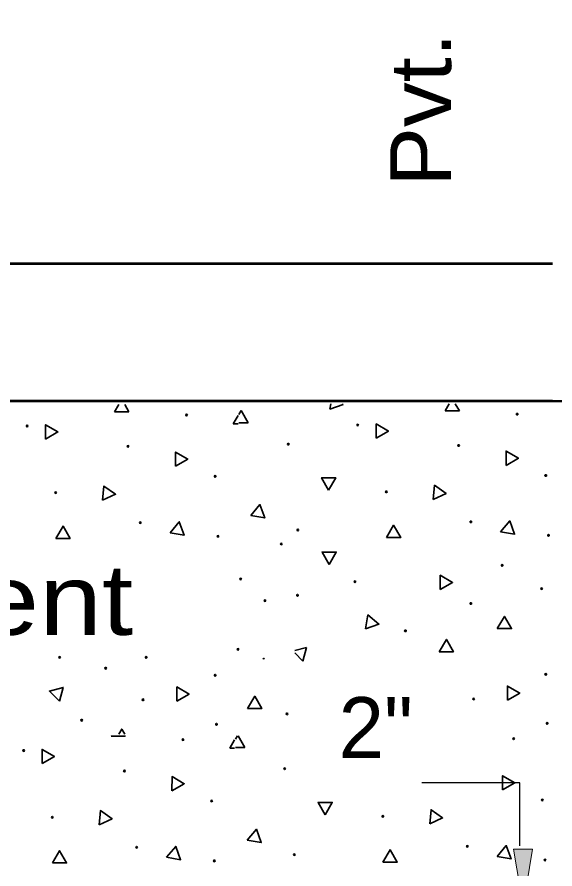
# Model space of a CAD drawing. Extents: x 72.6 to 107.3, y 36.1 to 58.1.
# Drawn here: x 92.859 to 94.034, y 53.623 to 55.484 of the extents above; entities that cross this region are included whole.
import ezdxf

# ---------------------------------------------------------------- set-up
doc = ezdxf.new("R2010")
doc.units = 0
doc.header["$LTSCALE"] = 0.053
doc.layers.add('1', color=7, linetype='Continuous', lineweight=35)
doc.layers.add('3', color=7, linetype='Continuous', lineweight=13)

msp = doc.modelspace()

# ---------------------------------------------------------------- hatches: boundary and pattern name
at = {"layer": '3'}
msp.add_hatch(color=256, dxfattribs=at).paths.add_polyline_path([(93.98483, 53.66683), (93.94317, 53.66683), (93.964, 53.54183), (93.964, 53.54183)])

# ---------------------------------------------------------------- linework, layer by layer
at = {"layer": '1', "lineweight": 53}
for p, q in [((90.01767, 54.94575), (94.0285, 54.94575)), ((90.01767, 54.94575), (94.0285, 54.94575)), ((90.01767, 54.64575), (94.0285, 54.64575))]:
    msp.add_line(p, q, dxfattribs=at)
at = {"layer": '1'}
for p, q in [((93.08117, 54.63742), (93.07217, 54.622)), ((93.08117, 54.63742), (93.07217, 54.622)), ((93.10333, 54.622), (93.09433, 54.63742)), ((93.10333, 54.622), (93.09433, 54.63742)), ((93.34867, 54.6245), (93.34367, 54.61583)), ((93.34867, 54.6245), (93.34367, 54.61583)), ((93.34867, 54.6245), (93.34367, 54.61583)), ((93.34867, 54.6245), (93.34367, 54.61583)), ((93.36417, 54.59767), (93.34867, 54.6245)), ((93.36417, 54.59767), (93.34867, 54.6245)), ((93.36417, 54.59767), (93.34867, 54.6245)), ((93.36417, 54.59767), (93.34867, 54.6245)), ((93.54433, 54.63933), (93.54217, 54.62717)), ((93.54433, 54.63933), (93.54217, 54.62717)), ((93.54433, 54.63933), (93.54217, 54.62717)), ((93.54433, 54.63933), (93.54217, 54.62717)), ((93.54217, 54.62717), (93.57133, 54.63783)), ((93.54217, 54.62717), (93.57133, 54.63783)), ((93.54217, 54.62717), (93.57133, 54.63783)), ((93.54217, 54.62717), (93.57133, 54.63783)), ((93.57133, 54.63783), (93.5695, 54.63933)), ((93.57133, 54.63783), (93.5695, 54.63933)), ((93.57133, 54.63783), (93.5695, 54.63933)), ((93.57133, 54.63783), (93.5695, 54.63933)), ((93.803, 54.63933), (93.794, 54.62392)), ((93.803, 54.63933), (93.794, 54.62392)), ((93.803, 54.63933), (93.794, 54.62392)), ((93.803, 54.63933), (93.794, 54.62392)), ((93.794, 54.62392), (93.82517, 54.62392)), ((93.794, 54.62392), (93.82517, 54.62392)), ((93.794, 54.62392), (93.82517, 54.62392)), ((93.794, 54.62392), (93.82517, 54.62392)), ((93.82517, 54.62392), (93.81617, 54.63933)), ((93.82517, 54.62392), (93.81617, 54.63933)), ((93.82517, 54.62392), (93.81617, 54.63933)), ((93.82517, 54.62392), (93.81617, 54.63933)), ((93.07217, 54.622), (93.10333, 54.622)), ((93.07217, 54.622), (93.10333, 54.622)), ((93.34183, 54.61392), (93.33125, 54.59575)), ((93.34183, 54.61392), (93.33125, 54.59575)), ((93.33125, 54.59575), (93.34183, 54.59575)), ((93.33125, 54.59575), (93.34183, 54.59575)), ((93.34367, 54.59767), (93.36417, 54.59767)), ((93.34367, 54.59767), (93.36417, 54.59767)), ((93.34367, 54.59767), (93.36417, 54.59767)), ((93.34367, 54.59767), (93.36417, 54.59767)), ((93.49158, 54.10717), (93.46567, 54.10025)), ((93.49158, 54.10717), (93.46567, 54.10025)), ((93.49158, 54.10717), (93.46567, 54.10025)), ((93.49158, 54.10717), (93.46567, 54.10025)), ((93.48358, 54.07717), (93.49158, 54.10717)), ((93.48358, 54.07717), (93.49158, 54.10717)), ((93.48358, 54.07717), (93.49158, 54.10717)), ((93.48358, 54.07717), (93.49158, 54.10717)), ((93.46567, 54.09517), (93.48358, 54.07717)), ((93.46567, 54.09517), (93.48358, 54.07717)), ((93.46567, 54.09517), (93.48358, 54.07717)), ((93.46567, 54.09517), (93.48358, 54.07717)), ((93.06517, 53.91433), (93.0645, 53.91317)), ((93.06517, 53.91433), (93.0645, 53.91317)), ((93.0645, 53.91317), (93.09567, 53.91317)), ((93.0645, 53.91317), (93.09567, 53.91317)), ((93.09567, 53.91317), (93.095, 53.91433)), ((93.09567, 53.91317), (93.095, 53.91433)), ((93.33417, 53.90508), (93.32358, 53.88692)), ((93.33417, 53.90508), (93.32358, 53.88692)), ((93.34025, 53.91433), (93.336, 53.907)), ((93.34025, 53.91433), (93.336, 53.907)), ((93.34025, 53.91433), (93.336, 53.907)), ((93.34025, 53.91433), (93.336, 53.907)), ((93.3565, 53.88883), (93.34175, 53.91433)), ((93.3565, 53.88883), (93.34175, 53.91433)), ((93.3565, 53.88883), (93.34175, 53.91433)), ((93.3565, 53.88883), (93.34175, 53.91433)), ((93.32358, 53.88692), (93.33417, 53.88692)), ((93.32358, 53.88692), (93.33417, 53.88692)), ((93.336, 53.88883), (93.3565, 53.88883)), ((93.336, 53.88883), (93.3565, 53.88883)), ((93.336, 53.88883), (93.3565, 53.88883)), ((93.336, 53.88883), (93.3565, 53.88883))]:
    msp.add_line(p, q, dxfattribs=at)
at = {"layer": '1', "lineweight": 25}
msp.add_line((93.957, 53.81142), (93.74308, 53.81142), dxfattribs=at)
at = {"layer": '1', "lineweight": 53}
msp.add_lwpolyline([(90.01767, 54.64575), (94.0285, 54.64575), (97.54775, 54.52283)], dxfattribs=at)
msp.add_lwpolyline([(90.01767, 54.64575), (94.0285, 54.64575), (97.54775, 54.52283)], dxfattribs=at)
at = {"layer": '1'}
for points in [[(92.9215, 54.56225), (92.94842, 54.57775), (92.92167, 54.59333)], [(92.9215, 54.56225), (92.94842, 54.57775), (92.92167, 54.59333)], [(93.64333, 54.56417), (93.67025, 54.57967), (93.6435, 54.59525)], [(93.64333, 54.56417), (93.67025, 54.57967), (93.6435, 54.59525)], [(93.64333, 54.56417), (93.67025, 54.57967), (93.6435, 54.59525)], [(93.64333, 54.56417), (93.67025, 54.57967), (93.6435, 54.59525)], [(93.20517, 54.50275), (93.23208, 54.51833), (93.20533, 54.53392)], [(93.20517, 54.50275), (93.23208, 54.51833), (93.20533, 54.53392)], [(93.927, 54.50467), (93.95392, 54.52025), (93.92717, 54.53583)], [(93.927, 54.50467), (93.95392, 54.52025), (93.92717, 54.53583)], [(93.927, 54.50467), (93.95392, 54.52025), (93.92717, 54.53583)], [(93.927, 54.50467), (93.95392, 54.52025), (93.92717, 54.53583)], [(93.5395, 54.45075), (93.55517, 54.47767), (93.52408, 54.47767)], [(93.5395, 54.45075), (93.55517, 54.47767), (93.52408, 54.47767)], [(93.5395, 54.45075), (93.55517, 54.47767), (93.52408, 54.47767)], [(93.5395, 54.45075), (93.55517, 54.47767), (93.52408, 54.47767)], [(93.04617, 54.42867), (93.07433, 54.44175), (93.049, 54.45958)], [(93.04617, 54.42867), (93.07433, 54.44175), (93.049, 54.45958)], [(93.768, 54.43058), (93.79617, 54.44367), (93.77083, 54.4615)], [(93.768, 54.43058), (93.79617, 54.44367), (93.77083, 54.4615)], [(93.768, 54.43058), (93.79617, 54.44367), (93.77083, 54.4615)], [(93.768, 54.43058), (93.79617, 54.44367), (93.77083, 54.4615)], [(93.3695, 54.39533), (93.40008, 54.38992), (93.3895, 54.41908)], [(93.3695, 54.39533), (93.40008, 54.38992), (93.3895, 54.41908)], [(93.3695, 54.39533), (93.40008, 54.38992), (93.3895, 54.41908)], [(93.3695, 54.39533), (93.40008, 54.38992), (93.3895, 54.41908)], [(93.91517, 54.35958), (93.94567, 54.35417), (93.93508, 54.38342)], [(93.91517, 54.35958), (93.94567, 54.35417), (93.93508, 54.38342)], [(93.91517, 54.35958), (93.94567, 54.35417), (93.93508, 54.38342)], [(93.91517, 54.35958), (93.94567, 54.35417), (93.93508, 54.38342)], [(92.944, 54.34525), (92.97508, 54.34525), (92.95967, 54.37208)], [(92.944, 54.34525), (92.97508, 54.34525), (92.95967, 54.37208)], [(93.19333, 54.35767), (93.22383, 54.35225), (93.21325, 54.3815)], [(93.19333, 54.35767), (93.22383, 54.35225), (93.21325, 54.3815)], [(93.66583, 54.34717), (93.69692, 54.34717), (93.6815, 54.374)], [(93.66583, 54.34717), (93.69692, 54.34717), (93.6815, 54.374)], [(93.66583, 54.34717), (93.69692, 54.34717), (93.6815, 54.374)], [(93.66583, 54.34717), (93.69692, 54.34717), (93.6815, 54.374)], [(93.54075, 54.2885), (93.55633, 54.31542), (93.52525, 54.31542)], [(93.54075, 54.2885), (93.55633, 54.31542), (93.52525, 54.31542)], [(93.54075, 54.2885), (93.55633, 54.31542), (93.52525, 54.31542)], [(93.54075, 54.2885), (93.55633, 54.31542), (93.52525, 54.31542)], [(93.78317, 54.23375), (93.81008, 54.24925), (93.78325, 54.26483)], [(93.78317, 54.23375), (93.81008, 54.24925), (93.78325, 54.26483)], [(93.78317, 54.23375), (93.81008, 54.24925), (93.78325, 54.26483)], [(93.78317, 54.23375), (93.81008, 54.24925), (93.78325, 54.26483)], [(93.62008, 54.1475), (93.64925, 54.15817), (93.6255, 54.178)], [(93.62008, 54.1475), (93.64925, 54.15817), (93.6255, 54.178)], [(93.62008, 54.1475), (93.64925, 54.15817), (93.6255, 54.178)], [(93.62008, 54.1475), (93.64925, 54.15817), (93.6255, 54.178)], [(93.90783, 54.14817), (93.93883, 54.14817), (93.92342, 54.175)], [(93.90783, 54.14817), (93.93883, 54.14817), (93.92342, 54.175)], [(93.90783, 54.14817), (93.93883, 54.14817), (93.92342, 54.175)], [(93.90783, 54.14817), (93.93883, 54.14817), (93.92342, 54.175)], [(93.78108, 54.09783), (93.81217, 54.09783), (93.79667, 54.12467)], [(93.78108, 54.09783), (93.81217, 54.09783), (93.79667, 54.12467)], [(93.78108, 54.09783), (93.81217, 54.09783), (93.79667, 54.12467)], [(93.78108, 54.09783), (93.81217, 54.09783), (93.79667, 54.12467)], [(92.952, 53.98983), (92.96, 54.01992), (92.93008, 54.01192)], [(92.952, 53.98983), (92.96, 54.01992), (92.93008, 54.01192)], [(93.208, 53.98992), (93.235, 54.00542), (93.20825, 54.02092)], [(93.208, 53.98992), (93.235, 54.00542), (93.20825, 54.02092)], [(93.92983, 53.99183), (93.95683, 54.00733), (93.93008, 54.02283)], [(93.92983, 53.99183), (93.95683, 54.00733), (93.93008, 54.02283)], [(93.92983, 53.99183), (93.95683, 54.00733), (93.93008, 54.02283)], [(93.92983, 53.99183), (93.95683, 54.00733), (93.93008, 54.02283)], [(93.3625, 53.97367), (93.39358, 53.97367), (93.37817, 54.0005)], [(93.3625, 53.97367), (93.39358, 53.97367), (93.37817, 54.0005)], [(93.3625, 53.97367), (93.39358, 53.97367), (93.37817, 54.0005)], [(93.3625, 53.97367), (93.39358, 53.97367), (93.37817, 54.0005)], [(92.91383, 53.85342), (92.94075, 53.86892), (92.914, 53.8845)], [(92.91383, 53.85342), (92.94075, 53.86892), (92.914, 53.8845)], [(93.1975, 53.79392), (93.22442, 53.8095), (93.19767, 53.82508)], [(93.1975, 53.79392), (93.22442, 53.8095), (93.19767, 53.82508)], [(93.91933, 53.79583), (93.94625, 53.81142), (93.9195, 53.827)], [(93.91933, 53.79583), (93.94625, 53.81142), (93.9195, 53.827)], [(93.91933, 53.79583), (93.94625, 53.81142), (93.9195, 53.827)], [(93.91933, 53.79583), (93.94625, 53.81142), (93.9195, 53.827)], [(93.53183, 53.74192), (93.5475, 53.76883), (93.51642, 53.76883)], [(93.53183, 53.74192), (93.5475, 53.76883), (93.51642, 53.76883)], [(93.53183, 53.74192), (93.5475, 53.76883), (93.51642, 53.76883)], [(93.53183, 53.74192), (93.5475, 53.76883), (93.51642, 53.76883)], [(93.0385, 53.71983), (93.06667, 53.73292), (93.04133, 53.75075)], [(93.0385, 53.71983), (93.06667, 53.73292), (93.04133, 53.75075)], [(93.76033, 53.72175), (93.7885, 53.73483), (93.76317, 53.75267)], [(93.76033, 53.72175), (93.7885, 53.73483), (93.76317, 53.75267)], [(93.76033, 53.72175), (93.7885, 53.73483), (93.76317, 53.75267)], [(93.76033, 53.72175), (93.7885, 53.73483), (93.76317, 53.75267)], [(93.36183, 53.6865), (93.39242, 53.68108), (93.38183, 53.71025)], [(93.36183, 53.6865), (93.39242, 53.68108), (93.38183, 53.71025)], [(93.36183, 53.6865), (93.39242, 53.68108), (93.38183, 53.71025)], [(93.36183, 53.6865), (93.39242, 53.68108), (93.38183, 53.71025)], [(92.93633, 53.63642), (92.96742, 53.63642), (92.952, 53.66325)], [(92.93633, 53.63642), (92.96742, 53.63642), (92.952, 53.66325)], [(93.18567, 53.64883), (93.21617, 53.64342), (93.20558, 53.67267)], [(93.18567, 53.64883), (93.21617, 53.64342), (93.20558, 53.67267)], [(93.65817, 53.63833), (93.68925, 53.63833), (93.67383, 53.66517)], [(93.65817, 53.63833), (93.68925, 53.63833), (93.67383, 53.66517)], [(93.65817, 53.63833), (93.68925, 53.63833), (93.67383, 53.66517)], [(93.65817, 53.63833), (93.68925, 53.63833), (93.67383, 53.66517)], [(93.9075, 53.65075), (93.938, 53.64533), (93.92742, 53.67458)], [(93.9075, 53.65075), (93.938, 53.64533), (93.92742, 53.67458)], [(93.9075, 53.65075), (93.938, 53.64533), (93.92742, 53.67458)], [(93.9075, 53.65075), (93.938, 53.64533), (93.92742, 53.67458)]]:
    msp.add_lwpolyline(points, close=True, dxfattribs=at)
msp.add_lwpolyline([(93.09433, 53.91742), (93.08775, 53.92883), (93.08117, 53.91742)], dxfattribs=at)
msp.add_lwpolyline([(93.09433, 53.91742), (93.08775, 53.92883), (93.08117, 53.91742)], dxfattribs=at)
for centre in [(93.22933, 54.61462), (93.22933, 54.61462), (93.95117, 54.61653), (93.95117, 54.61653), (93.95117, 54.61653), (93.95117, 54.61653), (92.88127, 54.5908), (92.88127, 54.5908), (93.60311, 54.59271), (93.60311, 54.59271), (93.60311, 54.59271), (93.60311, 54.59271), (93.45137, 54.55107), (93.45137, 54.55107), (93.45137, 54.55107), (93.45137, 54.55107), (93.82325, 54.54813), (93.82325, 54.54813), (93.82325, 54.54813), (93.82325, 54.54813), (93.10141, 54.54622), (93.10141, 54.54622), (93.29185, 54.48076), (93.29185, 54.48076), (94.01369, 54.48267), (94.01369, 54.48267), (94.01369, 54.48267), (94.01369, 54.48267), (92.94373, 54.44506), (92.94373, 54.44506), (93.66557, 54.44697), (93.66557, 54.44697), (93.66557, 54.44697), (93.66557, 54.44697), (93.85007, 54.38151), (93.85007, 54.38151), (93.85007, 54.38151), (93.85007, 54.38151), (93.12823, 54.3796), (93.12823, 54.3796), (93.47225, 54.36363), (93.47225, 54.36363), (93.47225, 54.36363), (93.47225, 54.36363), (93.29779, 54.34984), (93.29779, 54.34984), (94.01963, 54.35175), (94.01963, 54.35175), (94.01963, 54.35175), (94.01963, 54.35175), (93.43609, 54.33317), (93.91847, 54.28629), (93.91847, 54.28629), (93.91847, 54.28629), (93.91847, 54.28629), (93.34759, 54.2565), (93.59717, 54.25059), (93.59717, 54.25059), (93.59717, 54.25059), (93.59717, 54.25059), (94.00475, 54.23571), (94.00475, 54.23571), (94.00475, 54.23571), (94.00475, 54.23571), (93.47151, 54.22109), (93.40067, 54.20925), (93.85007, 54.20301), (93.85007, 54.20301), (93.85007, 54.20301), (93.85007, 54.20301), (93.70727, 54.14349), (93.70727, 54.14349), (93.70727, 54.14349), (93.70727, 54.14349), (93.34167, 54.103), (92.95242, 54.08534), (93.14117, 54.08534), (93.05267, 54.06175), (93.29185, 54.04642), (93.29185, 54.04642), (94.01369, 54.04833), (94.01369, 54.04833), (94.01369, 54.04833), (94.01369, 54.04833), (93.13417, 53.99284), (93.13417, 53.99284), (93.85601, 53.99475), (93.85601, 53.99475), (93.85601, 53.99475), (93.85601, 53.99475), (93.44843, 53.96205), (93.44843, 53.96205), (93.44843, 53.96205), (93.44843, 53.96205), (93.00031, 53.9482), (93.00031, 53.9482), (93.29479, 53.93932), (93.29479, 53.93932), (94.01663, 53.94123), (94.01663, 53.94123), (94.01663, 53.94123), (94.01663, 53.94123), (93.22167, 53.90578), (93.22167, 53.90578), (93.9435, 53.9077), (93.9435, 53.9077), (93.9435, 53.9077), (93.9435, 53.9077), (92.87361, 53.88196), (92.87361, 53.88196), (93.4437, 53.84224), (93.4437, 53.84224), (93.4437, 53.84224), (93.4437, 53.84224), (93.09375, 53.83738), (93.09375, 53.83738), (93.28419, 53.77192), (93.28419, 53.77192), (94.00602, 53.77384), (94.00602, 53.77384), (94.00602, 53.77384), (94.00602, 53.77384), (92.93607, 53.73622), (92.93607, 53.73622), (93.6579, 53.73814), (93.6579, 53.73814), (93.6579, 53.73814), (93.6579, 53.73814), (93.12057, 53.67076), (93.12057, 53.67076), (93.46458, 53.6548), (93.46458, 53.6548), (93.46458, 53.6548), (93.46458, 53.6548), (93.8424, 53.67268), (93.8424, 53.67268), (93.8424, 53.67268), (93.8424, 53.67268), (93.29013, 53.641), (93.29013, 53.641), (94.01196, 53.64292), (94.01196, 53.64292), (94.01196, 53.64292), (94.01196, 53.64292)]:
    msp.add_circle(centre, 0.00173, dxfattribs=at)
msp.add_arc((93.39785, 54.08403), 0.00173, 181.10664, 358.89336, dxfattribs=at)
msp.add_arc((93.39785, 54.08403), 0.00173, 181.10664, 358.89336, dxfattribs=at)
msp.add_arc((93.39785, 54.08403), 0.00173, 181.10664, 358.89336, dxfattribs=at)
msp.add_arc((93.39785, 54.08403), 0.00173, 181.10664, 358.89336, dxfattribs=at)
at = {"layer": '3', "lineweight": 25}
msp.add_line((93.957, 53.674), (93.957, 53.81142), dxfattribs=at)
at = {"layer": '3'}
msp.add_lwpolyline([(93.98483, 53.66683), (93.94317, 53.66683), (93.964, 53.54183), (93.964, 53.54183)], close=True, dxfattribs=at)

# ---------------------------------------------------------------- texts
at = {"layer": '1', "width": 1.1}
msp.add_text('Pvt. edge', height=0.133, rotation=90, dxfattribs=at).set_placement((93.80708, 55.11317))
at = {"layer": '3', "width": 1.2}
msp.add_text('Existing  pavement', height=0.1536, dxfattribs=at).set_placement((91.03067, 54.1345))
at = {"layer": '3'}
msp.add_text('2"', height=0.133, dxfattribs=at).set_placement((93.5615, 53.86558))

doc.saveas('drawing.dxf')
